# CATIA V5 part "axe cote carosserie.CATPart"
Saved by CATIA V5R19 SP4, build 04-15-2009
Part number: axe coté porte
Bounding box of the stored display mesh (mm): x 0 to 175.61, y -12.497 to 12.503, z -12.163 to 12.458
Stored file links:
  G:\EU_thinkMotion\CFAO_2010\MMS_groupe1\MMS_groupe1\A reprendre\OK\rdeneffle\axe cote carosserie.CATPart
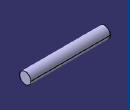
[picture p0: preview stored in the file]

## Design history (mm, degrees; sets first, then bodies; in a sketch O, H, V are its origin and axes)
Body1 (main body)
  Sketch1 on yz-plane, origin (0, 0, 0), H (0, 1, 0), V (0, 0, 1)
    circle A1 centre (0.0034, 0.1475) radius 12.5
    radius A1 = 12.5
  Pad1: profile Sketch1, direction (1, 0, 0), length 175.61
